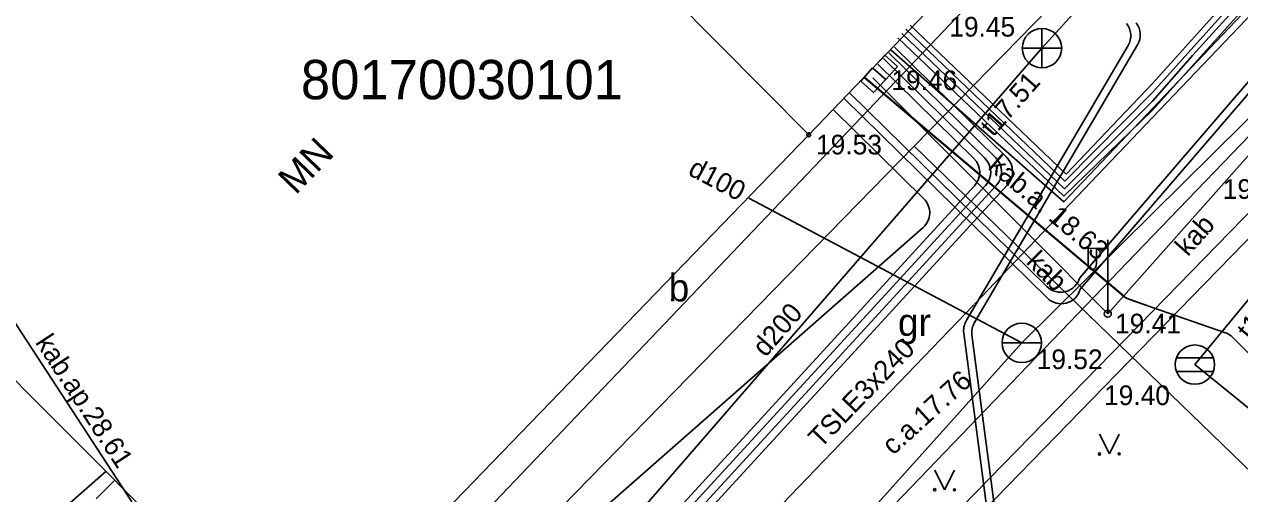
# Model space of a CAD drawing. Extents: x 532933 to 533143, y 328014 to 328163.
# Drawn here: x 532971.35 to 533002.21, y 328062.57 to 328074.5 of the extents above; entities that cross this region are included whole.
import ezdxf

# ---------------------------------------------------------------- set-up
doc = ezdxf.new("R2010")
doc.units = 0
for name, color, linetype in [('APGS_ELEM_####_####_#', 7, 'Continuous'), ('APGS_VADV_ZSPR_####_#', 7, 'Continuous'), ('APGS_VADV_ZSPR_TKST_#', 7, 'Continuous'), ('BUVE_BDET_####_####_#', 7, 'Continuous'), ('BUVE_EKAS_####_####_#', 7, 'Continuous'), ('BUVE_EKAS_RAKS_TKST_#', 7, 'Continuous'), ('CELI_CMAL_####_####_#', 7, 'Continuous'), ('CELI_CSEG_####_TKST_#', 7, 'Continuous'), ('ELEK_ACRL_####_####_#', 7, 'Continuous'), ('ELEK_ELEM_####_####_#', 7, 'Continuous'), ('ELEK_STTP_####_####_#', 7, 'Continuous'), ('ELEK_VADP_NEDR_####_#', 7, 'Continuous'), ('ELEK_VADP_VSPR_####_#', 7, 'Continuous'), ('ELEK_VADP_VSPR_TKST_#', 7, 'Continuous'), ('ELEK_VADP_ZSPR_####_#', 7, 'Continuous'), ('ELEK_VADP_ZSPR_TKST_#', 7, 'Continuous'), ('LKAN_ELEM_####_####_#', 7, 'Continuous'), ('LKAN_ELEM_PAST_TKST_#', 7, 'Continuous'), ('LKAN_VADP_PAST_####_#', 7, 'Continuous'), ('LKAN_VADP_PAST_TKST_#', 7, 'Continuous'), ('NORB_ZOGS_ZSTP_####_#', 7, 'Continuous'), ('RELJ_AATZ_####_TKST_#', 7, 'Continuous'), ('RELJ_ELEM_####_####_#', 7, 'Continuous'), ('ROBZ_UZMR_####_####_#', 7, 'Continuous'), ('ROBZ_UZMR_####_TKST_#', 7, 'Continuous'), ('SAKT_VADV_PKAB_####_#', 7, 'Continuous'), ('SAKT_VADV_PKAB_TKST_#', 7, 'Continuous'), ('SKAN_ELEM_####_####_#', 7, 'Continuous'), ('SKAN_ELEM_PAST_TKST_#', 7, 'Continuous'), ('SKAN_VADP_PAST_####_#', 7, 'Continuous'), ('SKAN_VADP_PAST_TKST_#', 7, 'Continuous'), ('TERT_ELEM_####_####_#', 7, 'Continuous'), ('UDTK_ELEM_####_####_#', 7, 'Continuous'), ('UDTK_ELEM_####_TKST_#', 7, 'Continuous'), ('UDTK_VADP_UDEN_####_#', 7, 'Continuous'), ('UDTK_VADP_UDEN_TKST_#', 7, 'Continuous')]:
    doc.layers.add(name, color=color, linetype=linetype)

msp = doc.modelspace()

# ---------------------------------------------------------------- linework, layer by layer
at = {"layer": 'APGS_ELEM_####_####_#'}
for p, q in [((532998.864, 328067.143), (532998.864, 328069.025)), ((532998.864, 328068.809), (532998.229, 328068.804)), ((532998.364, 328068.805), (532998.364, 328068.413)), ((532998.574, 328068.807), (532998.574, 328068.413))]:
    msp.add_line(p, q, dxfattribs=at)
msp.add_lwpolyline([(532993.219, 328073.092), (532992.918, 328072.762), (532992.593, 328073.058), (532992.894, 328073.389)], close=True, dxfattribs=at)
msp.add_circle((532998.864, 328067.143), 0.09, dxfattribs=at)
msp.add_ellipse((532998.469, 328068.413), major_axis=(0, 0.151), ratio=0.695971, start_param=1.570796, end_param=4.712389, dxfattribs=at)
at = {"layer": 'APGS_VADV_ZSPR_####_#'}
for points in [[(533035.157, 328119.006), (533019.905, 328090.862), (533000, 328068.423)], [(533000, 328068.423), (532998.864, 328067.143), (532992.901, 328073.14)]]:
    msp.add_lwpolyline(points, dxfattribs=at)
at = {"layer": 'BUVE_BDET_####_####_#'}
msp.add_line((532973.651, 328062.91), (532973.174, 328062.438), dxfattribs=at)
msp.add_lwpolyline([(532973.427, 328063.138), (532969.826, 328059.969), (532963.605, 328066.425), (532962.603, 328070.346), (532963.994, 328070.869)], dxfattribs=at)
at = {"layer": 'BUVE_EKAS_####_####_#'}
for p, q in [((532984.51, 328078.518), (532991.271, 328071.691)), ((532991.271, 328071.691), (532978.273, 328058.231)), ((532978.273, 328058.231), (532973.38, 328063.184))]:
    msp.add_line(p, q, dxfattribs=at)
msp.add_lwpolyline([(532964.233, 328071.04), (532964.63, 328071.455), (532969.135, 328067.437), (532973.381, 328063.184)], dxfattribs=at)
at = {"layer": 'CELI_CMAL_####_####_#'}
for points in [[(532982.259, 328061.27), (532998.656, 328078.496)], [(533000, 328066.543), (533004.338, 328071.006), (533009.227, 328055.441), (533009.695, 328055.597), (533004.734, 328071.393), (533007.479, 328074.224), (533007.765, 328073.914), (533008.143, 328074.297)], [(533002.625, 328069.891), (533000, 328067.199)], [(533000, 328067.199), (532988.954, 328055.872), (532989.285, 328055.52), (533000, 328066.543)]]:
    msp.add_lwpolyline(points, dxfattribs=at)
at = {"layer": 'ELEK_ACRL_####_####_#'}
for p, q in [((532992.693, 328073.148), (532999.281, 328067.585)), ((532999.44, 328067.494), (533000, 328067.3)), ((533000, 328067.3), (533001.851, 328066.659)), ((533002.043, 328066.538), (533005.58, 328062.956))]:
    msp.add_line(p, q, dxfattribs=at)
for centre, start, end in [((532999.604, 328067.967), 229.8208, 250.8941), ((533001.687, 328066.187), 44.6387, 70.8941)]:
    msp.add_arc(centre, 0.5, start, end, dxfattribs=at)
at = {"layer": 'ELEK_ELEM_####_####_#'}
msp.add_lwpolyline([(532993.527, 328073.425), (532993.228, 328073.093), (532992.901, 328073.387), (532993.2, 328073.719)], close=True, dxfattribs=at)
at = {"layer": 'ELEK_STTP_####_####_#'}
msp.add_line((532991.271, 328071.691), (532997.829, 328078.537), dxfattribs=at)
at = {"layer": 'ELEK_VADP_NEDR_####_#'}
for p, q in [((532993.447, 328073.916), (532996.298, 328071.111)), ((532993.167, 328073.63), (532995.742, 328071.096)), ((532993.307, 328073.773), (532996.02, 328071.104)), ((532993.026, 328073.488), (532995.465, 328071.089))]:
    msp.add_line(p, q, dxfattribs=at)
for points in [[(532996.316, 328070.417), (532986.502, 328059.706)], [(532995.483, 328070.395), (532985.678, 328059.695)], [(532995.76, 328070.402), (532985.952, 328059.699)], [(532996.038, 328070.409), (532986.227, 328059.702)]]:
    msp.add_lwpolyline(points, dxfattribs=at)
for centre in [(532995.114, 328070.733), (532995.392, 328070.74), (532995.67, 328070.747), (532995.948, 328070.754)]:
    msp.add_arc(centre, 0.5, 317.4991, 45.467, dxfattribs=at)
at = {"layer": 'ELEK_VADP_VSPR_####_#'}
for p, q in [((533000, 328072.134), (533007.306, 328079.806)), ((532995.481, 328067.388), (533000, 328072.134)), ((532983.183, 328054.585), (532995.463, 328067.37))]:
    msp.add_line(p, q, dxfattribs=at)
for points in [[(532995.272, 328066.964), (532999.38, 328073.961)], [(532995.479, 328066.922), (532999.621, 328073.976)], [(532996.123, 328059.666), (532995.207, 328066.646)], [(532996.334, 328059.596), (532995.415, 328066.604)]]:
    msp.add_lwpolyline(points, dxfattribs=at)
for centre, start, end in [((532998.948, 328074.214), 329.5845, 37.7118), ((532999.189, 328074.23), 329.5845, 37.7118), ((532995.703, 328066.711), 149.5845, 187.4718), ((532995.91, 328066.669), 149.5845, 187.4718)]:
    msp.add_arc(centre, 0.5, start, end, dxfattribs=at)
at = {"layer": 'ELEK_VADP_ZSPR_####_#'}
for p, q in [((533015.085, 328089.795), (533000, 328072.993)), ((533015.178, 328089.675), (533000, 328072.768)), ((533015.366, 328089.434), (533000, 328072.319)), ((532997.812, 328070.688), (532993.844, 328074.48)), ((532997.748, 328070.127), (532993.531, 328074.157)), ((532997.766, 328070.316), (532993.635, 328074.265)), ((532997.775, 328070.516), (532993.739, 328074.372)), ((533000, 328072.993), (532997.812, 328070.688)), ((532992.17, 328072.617), (532997.33, 328067.54)), ((532992.31, 328072.76), (532997.318, 328067.832)), ((533000, 328072.768), (532997.775, 328070.516)), ((532991.889, 328072.332), (532994.195, 328070.063)), ((533000, 328072.319), (532997.748, 328070.127)), ((532999.987, 328072.529), (532997.766, 328070.316)), ((533000, 328067.3), (533001.851, 328066.659)), ((533002.043, 328066.538), (533005.58, 328062.956))]:
    msp.add_line(p, q, dxfattribs=at)
for points in [[(533015.32, 328089.608), (533004.957, 328078.053), (533004.027, 328077.035), (533001.028, 328073.711), (533000, 328072.544)], [(533000, 328070.209), (533009.856, 328081.68), (533016.021, 328088.594)], [(533000, 328069.902), (533010.007, 328081.549), (533016.146, 328088.434)], [(533000, 328072.357), (533007.294, 328080.052)], [(532993.364, 328073.839), (532997.75, 328069.983), (533000, 328072.357)], [(532992.682, 328073.148), (532999.312, 328067.55), (533000, 328067.305)], [(533000, 328072.544), (532999.987, 328072.529)], [(532998.151, 328068.057), (533000, 328070.209)], [(532998.163, 328067.764), (533000, 328069.902)], [(532994.175, 328069.331), (532985.231, 328061.466)]]:
    msp.add_lwpolyline(points, dxfattribs=at)
for centre, start, end in [((532993.844, 328069.707), 311.3292, 45.467), ((532997.669, 328068.189), 225.467, 344.7388), ((532997.681, 328067.896), 225.467, 344.7113), ((533001.687, 328066.187), 44.6387, 70.8939)]:
    msp.add_arc(centre, 0.5, start, end, dxfattribs=at)
at = {"layer": 'LKAN_ELEM_####_####_#'}
for p, q in [((533000.608, 328066.023), (533001.544, 328066.023)), ((533000.608, 328065.673), (533001.544, 328065.673))]:
    msp.add_line(p, q, dxfattribs=at)
msp.add_circle((533001.076, 328065.848), 0.5, dxfattribs=at)
at = {"layer": 'LKAN_VADP_PAST_####_#'}
for p, q in [((533007.318, 328073.453), (533001.076, 328065.848)), ((533001.076, 328065.848), (533006.239, 328061.66))]:
    msp.add_line(p, q, dxfattribs=at)
at = {"layer": 'NORB_ZOGS_ZSTP_####_#'}
for p, q in [((533000, 328069.113), (533006.279, 328075.645)), ((532988.134, 328056.767), (533000, 328069.113))]:
    msp.add_line(p, q, dxfattribs=at)
at = {"layer": 'RELJ_ELEM_####_####_#'}
msp.add_circle((532991.271, 328071.691), 0.05, dxfattribs=at)
at = {"layer": 'ROBZ_UZMR_####_####_#'}
for points in [[(532993.949, 328071.405), (532999.253, 328076.841), (533001.874, 328079.871), (533025.763, 328107.492), (533029.138, 328104.514), (533014.917, 328088.072), (533037.903, 328068.645), (533030.421, 328036.082)], [(532954.932, 328051.068), (532962.791, 328075.982), (532977.358, 328090.737), (532984.352, 328083.929), (532990.879, 328090.61), (533001.874, 328079.871), (532999.253, 328076.841), (532993.949, 328071.405), (532979.271, 328056.364), (532968.026, 328044.841)], [(532979.271, 328056.364), (532993.949, 328071.405), (533030.421, 328036.082), (533029.157, 328030.58), (533020.389, 328026.352), (532998.604, 328038.086)]]:
    msp.add_lwpolyline(points, close=True, dxfattribs=at)
at = {"layer": 'SAKT_VADV_PKAB_####_#'}
msp.add_line((532957.876, 328087.235), (532974.079, 328062.362), dxfattribs=at)
at = {"layer": 'SKAN_ELEM_####_####_#'}
for p, q in [((532997.194, 328073.392), (532997.194, 328074.392)), ((532996.694, 328073.892), (532997.694, 328073.892))]:
    msp.add_line(p, q, dxfattribs=at)
msp.add_circle((532997.194, 328073.892), 0.5, dxfattribs=at)
at = {"layer": 'SKAN_VADP_PAST_####_#'}
msp.add_lwpolyline([(533000, 328076.986), (532997.194, 328073.892), (532983.572, 328058.168), (532980.848, 328060.709)], dxfattribs=at)
at = {"layer": 'TERT_ELEM_####_####_#'}
for p, q in [((532998.655, 328064.08), (532998.905, 328063.58)), ((532998.905, 328063.58), (532999.155, 328064.08)), ((532994.47, 328063.168), (532994.72, 328062.668)), ((532994.72, 328062.668), (532994.97, 328063.168))]:
    msp.add_line(p, q, dxfattribs=at)
for centre, radius in [((532998.655, 328063.579), 0.028), ((532999.155, 328063.579), 0.0263), ((532994.47, 328062.668), 0.028), ((532994.97, 328062.668), 0.0263)]:
    msp.add_circle(centre, radius, dxfattribs=at)
at = {"layer": 'UDTK_ELEM_####_####_#'}
msp.add_line((532996.181, 328066.401), (532997.181, 328066.401), dxfattribs=at)
msp.add_circle((532996.681, 328066.401), 0.5, dxfattribs=at)
at = {"layer": 'UDTK_VADP_UDEN_####_#'}
for points in [[(533000, 328069.689), (533004.655, 328074.299), (533010.744, 328081.458)], [(532996.68, 328066.401), (532989.746, 328070.079)], [(532996.68, 328066.401), (533000, 328069.689)], [(532996.68, 328066.401), (532981.413, 328049.383), (532974.784, 328043.51)]]:
    msp.add_lwpolyline(points, dxfattribs=at)

# ---------------------------------------------------------------- texts
at = {"layer": 'APGS_VADV_ZSPR_TKST_#'}
for rotation, p in [(48.4244, (533000.898, 328068.576)), (314.839, (532996.769, 328068.44))]:
    msp.add_text('kab', height=0.5, rotation=rotation, dxfattribs=at).set_placement(p)
at = {"layer": 'BUVE_EKAS_RAKS_TKST_#'}
msp.add_text('MN', height=0.7, rotation=46.0015, dxfattribs=at).set_placement((532978.242, 328070.143))
at = {"layer": 'CELI_CSEG_####_TKST_#'}
for s, p in [(' b', (532987.455, 328067.455)), ('gr', (532993.538, 328066.577))]:
    msp.add_text(s, height=0.7, dxfattribs=at).set_placement(p)
at = {"layer": 'ELEK_VADP_VSPR_TKST_#'}
msp.add_text('TSLE3x240', height=0.5, rotation=45.9685, dxfattribs=at).set_placement((532991.574, 328063.703))
at = {"layer": 'ELEK_VADP_ZSPR_TKST_#'}
msp.add_text('kab.a. 18.63', height=0.5, rotation=319.8208, dxfattribs=at).set_placement((532995.797, 328070.841))
at = {"layer": 'LKAN_ELEM_PAST_TKST_#'}
msp.add_text(' 19.40', height=0.5, dxfattribs=at).set_placement((532998.584, 328064.82))
at = {"layer": 'LKAN_VADP_PAST_TKST_#'}
msp.add_text('t17.22', height=0.5, rotation=50.154, dxfattribs=at).set_placement((533002.483, 328066.442))
at = {"layer": 'RELJ_AATZ_####_TKST_#'}
for s, p in [(' 19.46', (532993.182, 328072.826)), (' 19.53', (532991.271, 328071.192)), (' 19.32', (533001.598, 328070.062)), (' 19.41', (532998.864, 328066.643))]:
    msp.add_text(s, height=0.5, dxfattribs=at).set_placement(p)
at = {"layer": 'ROBZ_UZMR_####_TKST_#'}
msp.add_text('80170030101', height=1, dxfattribs=at).set_placement((532978.375, 328072.594))
at = {"layer": 'SAKT_VADV_PKAB_TKST_#'}
msp.add_text('kab.ap.28.61', height=0.5, rotation=303.0802, dxfattribs=at).set_placement((532971.618, 328066.415))
at = {"layer": 'SKAN_ELEM_PAST_TKST_#'}
msp.add_text(' 19.45', height=0.5, dxfattribs=at).set_placement((532994.654, 328074.187))
at = {"layer": 'SKAN_VADP_PAST_TKST_#'}
for s, rotation, p in [('t17.51', 48.7139, (532995.956, 328071.618)), ('d200', 49.0999, (532990.173, 328066.017))]:
    msp.add_text(s, height=0.5, rotation=rotation, dxfattribs=at).set_placement(p)
at = {"layer": 'UDTK_ELEM_####_TKST_#'}
msp.add_text(' 19.52', height=0.5, dxfattribs=at).set_placement((532996.874, 328065.735))
at = {"layer": 'UDTK_VADP_UDEN_TKST_#'}
for s, rotation, p in [('d100', 332.0566, (532988.178, 328070.689)), ('c.a.17.76', 42.2859, (532993.413, 328063.528))]:
    msp.add_text(s, height=0.5, rotation=rotation, dxfattribs=at).set_placement(p)

doc.saveas('drawing.dxf')
